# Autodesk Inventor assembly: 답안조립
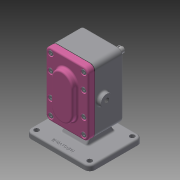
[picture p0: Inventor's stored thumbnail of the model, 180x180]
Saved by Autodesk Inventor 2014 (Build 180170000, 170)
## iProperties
Created: 2020-04
Part Number: 답안조립
Document SubType Name: Assembly
Designer: kh
Author: kh
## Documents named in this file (11)
- C:\Users\kh\Desktop\700407V1026\답안조립.iam
- C:\Users\kh\Desktop\700407V1026\본체.ipt
- C:\Users\kh\Desktop\700407V1026\개스킷.ipt
- C:\Users\kh\Desktop\700407V1026\메인축.ipt
- C:\Users\kh\Desktop\700407V1026\베어링부시.ipt
- C:\Users\kh\Desktop\700407V1026\볼트 M5.ipt
- C:\Users\kh\Desktop\700407V1026\서브축.ipt
- C:\Users\kh\Desktop\700407V1026\스퍼기어.ipt
- C:\Users\kh\Desktop\700407V1026\오일 실 16 28 7.ipt
- C:\Users\kh\Desktop\700407V1026\커버.ipt
- C:\Users\kh\Desktop\700407V1026\키 6 x 6 x 18.ipt
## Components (1 placed, 1 different names)
1. 개스킷:1
